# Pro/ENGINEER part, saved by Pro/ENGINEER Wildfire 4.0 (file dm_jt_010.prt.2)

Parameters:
  METRIC = "NO"

Other parameters: PITCH, DRILL_POINT_ANGLE, DRILL_DEPTH, DRILL_DIAMETER, THREAD_DIAMETER, THREADS_PER_INCH, THREAD_DEPTH, THREAD_LENGTH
